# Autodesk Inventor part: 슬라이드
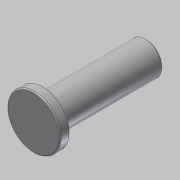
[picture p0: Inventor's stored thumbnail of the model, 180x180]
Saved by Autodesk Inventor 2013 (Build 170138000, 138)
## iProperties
Company: 한국ATC센터
Created: 2015-11
Part Number: 슬라이드
Document SubType Name: Modeling
Designer: mdu
Density: 7.86 g/cm^3
Material: 강철, 연강
Mass: 53.0481 g
Surface Area: 25.6984 cm^2
Volume: 6.74912 cm^3
Author: mdu
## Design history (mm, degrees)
sketch "스케치1"
  geometry: L1 (13.5, 41)-(13.5, 74) reference; L2 (13.5, 74)-(26.5, 74) reference; L3 (20, 74)-(20, 29); L4 (20, 74)-(13.5, 74); L5 (13.5, 74)-(13.5, 33); L6 (13.5, 33)-(9.5, 33); L7 (9.5, 33)-(9.5, 29); L8 (20, 73.5)-(13.5, 73.5); L9 (20, 29)-(9.5, 29); 1 further point
  constraints: 16 end point, 4 perpendicular, 3 point on line, 1 collinear, 1 midpoint, 1 parallel, 1 vertical, 2 other
  dimensions: "d0" = 45 distance of L3.start L3.end; "d1" = 21 diameter of L7 L3; "d2" = 4 distance from line of L3.end L6; "d4" = 0.5 distance between parallel lines of L8 L2
revolve "회전1" sketch "스케치1" stored, may be unused: angle "d5" = 90 deg
fillet "모깎기1" dims "d6" = 0.5
chamfer "모따기1" distance "d9" = 0.5; stored, may be unused: second distance "d10" = 2, angle "d11" = 45 deg
node "솔리드1"
node "참조1"
